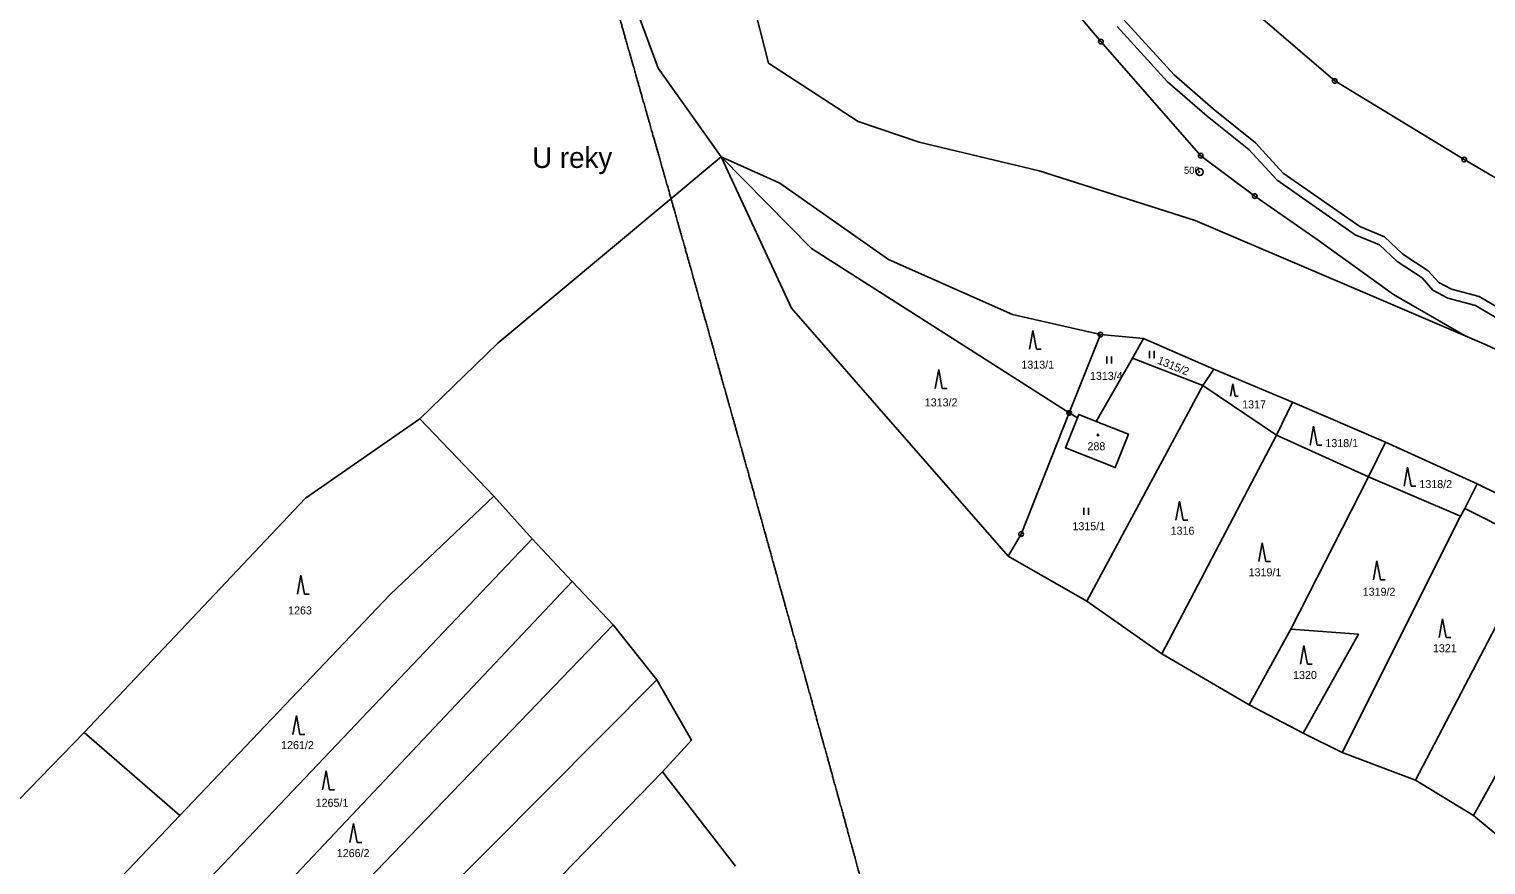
# Model space of a CAD drawing. Extents: x -680203 to -673936, y -1102717 to -1093650.
# Drawn here: x -676284 to -675974.5, y -1100041.7 to -1099864.2 of the extents above; entities that cross this region are included whole.
import ezdxf

# ---------------------------------------------------------------- set-up
doc = ezdxf.new("R2010")
doc.units = 0
for name, color, linetype in [('_Ideová část', 7, 'Continuous'), ('_Řešené území', 7, 'Continuous'), ('SOxx02xx_Koleje_param další_Popis10', 7, 'Continuous'), ('SOxx02xx_Staničení_Popis10', 7, 'Continuous'), ('SOxxxxxx_Koleje_hlavní_body_Popis10', 7, 'Continuous'), ('SOxxxxxx_Koleje_LN_parametry_Popis10', 7, 'Continuous'), ('SOxxxxxx_Koleje_param další_Popis10', 7, 'Continuous'), ('SOxxxxxx_Osa_bod_P', 7, 'Continuous'), ('x_prac', 7, 'Continuous')]:
    doc.layers.add(name, color=color, linetype=linetype)

msp = doc.modelspace()

# ---------------------------------------------------------------- linework, layer by layer
at = {"layer": '_Ideová část'}
msp.add_circle((-676417.7, -1099401.52), 1287.12, dxfattribs=at)
at = {"layer": '_Řešené území'}
for points in [[(-676159.4, -1099858.71), (-676158.26, -1099862.7), (-676157.11, -1099866.7), (-676155.97, -1099870.71)], [(-676155.97, -1099870.71), (-676154.83, -1099874.7), (-676153.69, -1099878.7), (-676152.55, -1099882.71)], [(-676152.55, -1099882.71), (-676151.41, -1099886.7), (-676150.28, -1099890.7), (-676149.14, -1099894.71)], [(-676149.14, -1099894.71), (-676148, -1099898.71), (-676146.87, -1099902.71), (-676145.73, -1099906.72)], [(-676145.73, -1099906.72), (-676144.6, -1099910.72), (-676143.47, -1099914.72), (-676142.34, -1099918.73)], [(-676142.34, -1099918.73), (-676141.21, -1099922.73), (-676140.08, -1099926.73), (-676138.95, -1099930.74)], [(-676138.95, -1099930.74), (-676137.82, -1099934.74), (-676136.7, -1099938.74), (-676135.57, -1099942.76)], [(-676135.57, -1099942.76), (-676134.45, -1099946.75), (-676133.32, -1099950.76), (-676132.2, -1099954.77)], [(-676132.2, -1099954.77), (-676131.08, -1099958.77), (-676129.96, -1099962.78), (-676128.83, -1099966.79)], [(-676128.83, -1099966.79), (-676127.72, -1099970.79), (-676126.6, -1099974.8), (-676125.48, -1099978.81)], [(-676125.48, -1099978.81), (-676124.37, -1099982.81), (-676123.25, -1099986.82), (-676122.13, -1099990.84)], [(-676122.13, -1099990.84), (-676121.02, -1099994.84), (-676119.91, -1099998.84), (-676118.8, -1100002.86)], [(-676118.8, -1100002.86), (-676117.69, -1100006.86), (-676116.58, -1100010.87), (-676115.47, -1100014.89)], [(-676115.47, -1100014.89), (-676114.36, -1100018.89), (-676113.25, -1100022.9), (-676112.14, -1100026.92)], [(-676112.14, -1100026.92), (-676111.04, -1100030.92), (-676109.94, -1100034.93), (-676108.83, -1100038.95)], [(-676108.83, -1100038.95), (-676107.73, -1100042.96), (-676106.63, -1100046.97), (-676105.53, -1100050.99)]]:
    msp.add_open_spline(points, degree=2, dxfattribs=at)
at = {"layer": 'SOxx02xx_Koleje_param další_Popis10'}
for centre, radius in [((-676056.24, -1099866.81), 0.5), ((-676056.24, -1099866.81), 0.0303), ((-676006.58, -1099875.18), 0.5), ((-676006.58, -1099875.18), 0.0303), ((-676035.03, -1099891.05), 0.5), ((-676035.03, -1099891.05), 0.0303), ((-675979.05, -1099891.89), 0.5), ((-675979.05, -1099891.89), 0.0303), ((-676035.26, -1099894.52), 0.75), ((-676035.26, -1099894.52), 0.03), ((-676023.56, -1099899.64), 0.5), ((-676023.56, -1099899.64), 0.0303), ((-676056.36, -1099929.04), 0.5), ((-676056.36, -1099929.04), 0.0303), ((-676062.99, -1099945.69), 0.5), ((-676062.99, -1099945.69), 0.0303), ((-676073.22, -1099971.41), 0.5), ((-676073.22, -1099971.41), 0.0303)]:
    msp.add_circle(centre, radius, dxfattribs=at)
at = {"layer": 'SOxxxxxx_Koleje_hlavní_body_Popis10'}
for p, q in [((-676070.69, -1099928.17), (-676071.44, -1099932.17)), ((-676069.94, -1099932.17), (-676070.69, -1099928.17)), ((-676069.94, -1099932.17), (-676068.94, -1099932.17)), ((-676045.94, -1099934.03), (-676045.94, -1099932.53)), ((-676044.94, -1099934.03), (-676044.94, -1099932.53)), ((-676090.7, -1099936.47), (-676091.45, -1099940.47)), ((-676089.95, -1099940.47), (-676090.7, -1099936.47)), ((-676055, -1099935.18), (-676055, -1099933.68)), ((-676054, -1099935.18), (-676054, -1099933.68)), ((-676028.24, -1099939.48), (-676028.74, -1099942.16)), ((-676027.74, -1099942.16), (-676028.24, -1099939.48)), ((-676089.95, -1099940.47), (-676088.95, -1099940.47)), ((-676027.74, -1099942.16), (-676027.07, -1099942.16)), ((-676011.06, -1099948.52), (-676011.81, -1099952.52)), ((-676010.31, -1099952.52), (-676011.06, -1099948.52)), ((-676010.31, -1099952.52), (-676009.31, -1099952.52)), ((-675991.09, -1099957.22), (-675991.84, -1099961.22)), ((-675990.34, -1099961.22), (-675991.09, -1099957.22)), ((-675990.34, -1099961.22), (-675989.34, -1099961.22)), ((-676059.86, -1099967.33), (-676059.86, -1099965.83)), ((-676058.86, -1099967.33), (-676058.86, -1099965.83)), ((-676039.55, -1099964.44), (-676040.3, -1099968.44)), ((-676038.8, -1099968.44), (-676039.55, -1099964.44)), ((-676038.8, -1099968.44), (-676037.8, -1099968.44)), ((-676021.98, -1099973.27), (-676022.73, -1099977.27)), ((-676021.23, -1099977.27), (-676021.98, -1099973.27)), ((-676021.23, -1099977.27), (-676020.23, -1099977.27)), ((-675997.62, -1099977.14), (-675998.37, -1099981.14)), ((-675996.87, -1099981.14), (-675997.62, -1099977.14)), ((-676226.2, -1099980.18), (-676226.95, -1099984.18)), ((-676225.45, -1099984.18), (-676226.2, -1099980.18)), ((-675996.87, -1099981.14), (-675995.87, -1099981.14)), ((-676225.45, -1099984.18), (-676224.45, -1099984.18)), ((-675983.67, -1099989.39), (-675984.42, -1099993.39)), ((-675982.92, -1099993.39), (-675983.67, -1099989.39)), ((-676013.13, -1099995.08), (-676013.88, -1099999.08)), ((-676012.38, -1099999.08), (-676013.13, -1099995.08)), ((-675982.92, -1099993.39), (-675981.92, -1099993.39)), ((-676012.38, -1099999.08), (-676011.38, -1099999.08)), ((-676227.17, -1100009.97), (-676227.92, -1100013.97)), ((-676226.42, -1100013.97), (-676227.17, -1100009.97)), ((-676226.42, -1100013.97), (-676225.42, -1100013.97)), ((-676220.86, -1100021.71), (-676221.61, -1100025.71)), ((-676220.11, -1100025.71), (-676220.86, -1100021.71)), ((-676220.11, -1100025.71), (-676219.11, -1100025.71)), ((-676215.04, -1100032.92), (-676215.79, -1100036.92)), ((-676214.29, -1100036.92), (-676215.04, -1100032.92)), ((-676214.29, -1100036.92), (-676213.29, -1100036.92))]:
    msp.add_line(p, q, dxfattribs=at)
at = {"layer": 'SOxxxxxx_Koleje_LN_parametry_Popis10'}
for points in [[(-676052.82, -1099863.62), (-676042.11, -1099875.34), (-676033.67, -1099882.65), (-676024.81, -1099889.77), (-676018.84, -1099896.28), (-676002.2, -1099907.86)], [(-675962.8, -1099928.71), (-675975.91, -1099920.99), (-675981.78, -1099919.43), (-675984.47, -1099918.02), (-675986.69, -1099915.48), (-675992.08, -1099911.97), (-675995.99, -1099908.29), (-676001.24, -1099906.1), (-676017.52, -1099894.76), (-676023.43, -1099888.31), (-676032.39, -1099881.11), (-676040.71, -1099873.9), (-676051.34, -1099862.26)], [(-676002.2, -1099907.86), (-675997.09, -1099909.99), (-675993.32, -1099913.55), (-675988.01, -1099917), (-675985.73, -1099919.62), (-675982.52, -1099921.31), (-675976.69, -1099922.85), (-675963.72, -1099930.49), (-675950.35, -1099936.38), (-675937.13, -1099943.88), (-675925.22, -1099950.4), (-675911.16, -1099956.48), (-675901.89, -1099961.49), (-675889.61, -1099968.11), (-675870.5, -1099977.94), (-675863.66, -1099981.35), (-675857.1, -1099984.63), (-675843.21, -1099991.31), (-675827.95, -1099999.23), (-675822.45, -1100002.36), (-675819.13, -1100004.45), (-675815.83, -1100006.42), (-675808.49, -1100010.96), (-675793.05, -1100019.98)]]:
    msp.add_lwpolyline(points, dxfattribs=at)
at = {"layer": 'SOxxxxxx_Koleje_param další_Popis10'}
msp.add_circle((-676056.87, -1099950.37), 0.175, dxfattribs=at)
at = {"layer": 'x_prac'}
for p, q in [((-676062.99, -1099945.69), (-676056.36, -1099929.04)), ((-676056.36, -1099929.04), (-676047.18, -1099929.88)), ((-676047.18, -1099929.88), (-676049.56, -1099934.04)), ((-676032.24, -1099936.43), (-676047.18, -1099929.88)), ((-676049.56, -1099934.04), (-676057.25, -1099947.48)), ((-676034.63, -1099939.88), (-676049.56, -1099934.04)), ((-676034.63, -1099939.88), (-676032.24, -1099936.43)), ((-676015.58, -1099943.43), (-676032.24, -1099936.43)), ((-676059.24, -1099985.69), (-676034.63, -1099939.88)), ((-676018.95, -1099950.44), (-676034.63, -1099939.88)), ((-676073.22, -1099971.41), (-676062.99, -1099945.69)), ((-676061.26, -1099946.76), (-676062.99, -1099945.69)), ((-676018.95, -1099950.44), (-676015.58, -1099943.43)), ((-675995.77, -1099951.87), (-676015.58, -1099943.43)), ((-676185.2, -1099963.39), (-676200.98, -1099946.98)), ((-676043.28, -1099996.89), (-676018.95, -1099950.44)), ((-676018.95, -1099950.44), (-675999.41, -1099959.24)), ((-675999.41, -1099959.24), (-675995.77, -1099951.87)), ((-675976.32, -1099960.75), (-675995.77, -1099951.87)), ((-676015.93, -1099991.65), (-675999.41, -1099959.24)), ((-675999.41, -1099959.24), (-675979.87, -1099967.59)), ((-675978.9, -1099965.99), (-675976.32, -1099960.75)), ((-675960.87, -1099968.39), (-675976.32, -1099960.75)), ((-676177.08, -1099972.46), (-676185.2, -1099963.39)), ((-675979.87, -1099967.59), (-675978.9, -1099965.99)), ((-675963.36, -1099973.81), (-675978.9, -1099965.99)), ((-676005, -1100017.85), (-675979.87, -1099967.59)), ((-676263.53, -1100063.36), (-676177.08, -1099972.46)), ((-676168.62, -1099981.53), (-676177.08, -1099972.46)), ((-676075.98, -1099976.08), (-676073.22, -1099971.41)), ((-676059.24, -1099985.69), (-676075.98, -1099976.08)), ((-675989.38, -1100023.71), (-675963.36, -1099973.81)), ((-676257.03, -1100075.25), (-676168.62, -1099981.53)), ((-676159.86, -1099990.68), (-676168.62, -1099981.53)), ((-675977.12, -1100031.17), (-675948.97, -1099980.64)), ((-676043.28, -1099996.89), (-676059.24, -1099985.69)), ((-676254.56, -1100089.03), (-676159.86, -1099990.68)), ((-676150.59, -1100002.38), (-676159.86, -1099990.68)), ((-676024.72, -1100007.72), (-676015.93, -1099991.65)), ((-676024.72, -1100007.72), (-676043.28, -1099996.89)), ((-676013.26, -1100013.68), (-676024.72, -1100007.72)), ((-676327.02, -1100069.84), (-676272.3, -1100013.6)), ((-676251.94, -1100031.21), (-676272.3, -1100013.6)), ((-676005, -1100017.85), (-676013.26, -1100013.68)), ((-675989.38, -1100023.71), (-676005, -1100017.85)), ((-676181.13, -1100054.53), (-676149.37, -1100021.9)), ((-676133.9, -1100041.95), (-676149.37, -1100021.9)), ((-675977.12, -1100031.17), (-675989.38, -1100023.71)), ((-676251.94, -1100031.21), (-676283.72, -1100064.46)), ((-675964.81, -1100041.41), (-675977.12, -1100031.17))]:
    msp.add_line(p, q, dxfattribs=at)
for points in [[(-676136.92, -1099891.31), (-676150.34, -1099872.48), (-676174.34, -1099807.56), (-676189.96, -1099776.98), (-676210.15, -1099738.03), (-676236.4, -1099687.15), (-676258.35, -1099661.79), (-676281.13, -1099634.4), (-676310.99, -1099577.62), (-676343.06, -1099502.08), (-676371.06, -1099463.4), (-676414.83, -1099431.65), (-676528.16, -1099352.79), (-676653.08, -1099275.13), (-676685.89, -1099268.24), (-676728.97, -1099246.24)], [(-676199.67, -1099537.72), (-676191.18, -1099544.23), (-676184.32, -1099561.54), (-676154.89, -1099602.92), (-676148.21, -1099623.96), (-676138.79, -1099649.53), (-676132.07, -1099670.16), (-676120.64, -1099701.37), (-676108.14, -1099736.46), (-676092.98, -1099779.72), (-676083.74, -1099799.5), (-676060.28, -1099820.73), (-676037.23, -1099848.82), (-676006.58, -1099875.18), (-675979.05, -1099891.89), (-675951.53, -1099908.03), (-675897.37, -1099934.31), (-675867.27, -1099948.26), (-675853, -1099954.61), (-675776.91, -1099991.79)], [(-676117.71, -1099763.31), (-676102.33, -1099798.68), (-676094.68, -1099812.86), (-676085.91, -1099827.61), (-676074.87, -1099843.37), (-676065.95, -1099855.23), (-676056.24, -1099866.81), (-676035.03, -1099891.05), (-676023.56, -1099899.64), (-676010.31, -1099908.88), (-675994.07, -1099920.54), (-675978.88, -1099929.3)], [(-675978.88, -1099929.3), (-675999.65, -1099920.41), (-676036.21, -1099904.82), (-676069.38, -1099894.28), (-676094.9, -1099888.18), (-676107.83, -1099883.82), (-676126.91, -1099871.38), (-676129.61, -1099860.54), (-676133.99, -1099833.8), (-676139.1, -1099820.18), (-676144.04, -1099808.21), (-676153.36, -1099787.75)], [(-675978.88, -1099929.3), (-675999.65, -1099920.41), (-676036.21, -1099904.82), (-676069.38, -1099894.28), (-676094.9, -1099888.18), (-676107.83, -1099883.82), (-676126.91, -1099871.38), (-676129.61, -1099860.54), (-676133.99, -1099833.8), (-676139.1, -1099820.18), (-676144.04, -1099808.21), (-676153.36, -1099787.75)], [(-676200.98, -1099946.98), (-676184.37, -1099930.9), (-676136.92, -1099891.31)], [(-676075.98, -1099976.08), (-676121.96, -1099923.46), (-676136.92, -1099891.31)], [(-676136.92, -1099891.31), (-676117.72, -1099910.75), (-676079.88, -1099934.93), (-676062.99, -1099945.69)], [(-676056.36, -1099929.04), (-676075.04, -1099924.81), (-676101.4, -1099913.11), (-676124.45, -1099896.91), (-676136.92, -1099891.31)], [(-675978.88, -1099929.3), (-675974.37, -1099931.23), (-675931.49, -1099951.16), (-675906.96, -1099963.1), (-675861.46, -1099988.51), (-675843.68, -1099998.35), (-675832.62, -1100005.56), (-675812.15, -1100019.19), (-675802.21, -1100030.11), (-675777.48, -1100056.88), (-675763.27, -1100074.81), (-675746.73, -1100095.56), (-675716.37, -1100123.87), (-675677.09, -1100159.95), (-675660.84, -1100178.25), (-675650.93, -1100184.82), (-675626.35, -1100211.55)], [(-675978.88, -1099929.3), (-675974.37, -1099931.23), (-675931.49, -1099951.16), (-675906.96, -1099963.1), (-675861.46, -1099988.51), (-675843.68, -1099998.35), (-675832.62, -1100005.56), (-675812.15, -1100019.19), (-675802.21, -1100030.11), (-675777.48, -1100056.88), (-675763.27, -1100074.81), (-675746.73, -1100095.56), (-675716.37, -1100123.87), (-675677.09, -1100159.95), (-675660.84, -1100178.25), (-675650.93, -1100184.82), (-675626.35, -1100211.55)], [(-676272.3, -1100013.6), (-676225.26, -1099963.8), (-676200.98, -1099946.98)], [(-676061.26, -1099946.76), (-676063.78, -1099953.1), (-676053.2, -1099957.31), (-676050.38, -1099950.22), (-676057.25, -1099947.48)], [(-676057.25, -1099947.48), (-676060.96, -1099946), (-676061.26, -1099946.76)], [(-676185.2, -1099963.39), (-676207.29, -1099984.27), (-676251.94, -1100031.21)], [(-676015.93, -1099991.65), (-676001.55, -1099992.71), (-676013.26, -1100013.68)], [(-676264.58, -1100120.51), (-676209.8, -1100061.91), (-676150.59, -1100002.38)], [(-676149.37, -1100021.9), (-676143.2, -1100015.19), (-676150.59, -1100002.38)]]:
    msp.add_lwpolyline(points, dxfattribs=at)

# ---------------------------------------------------------------- texts
at = {"layer": 'SOxx02xx_Koleje_param další_Popis10'}
msp.add_text('506', height=1.5, dxfattribs=at).set_placement((-676038.6, -1099894.9))
at = {"layer": 'SOxx02xx_Staničení_Popis10'}
msp.add_text('U reky', height=4.4, dxfattribs=at).set_placement((-676177.08, -1099893.66))
at = {"layer": 'SOxxxxxx_Osa_bod_P'}
for s, p in [('1313/1', (-676073.15, -1099936.29)), ('1313/4', (-676058.58, -1099938.67)), ('1313/2', (-676093.68, -1099944.3)), ('1317', (-676026.24, -1099944.73)), ('288', (-676059.11, -1099953.62)), ('1318/1', (-676008.56, -1099952.95)), ('1318/2', (-675988.59, -1099961.65)), ('1315/1', (-676062.3, -1099970.6)), ('1316', (-676041.44, -1099971.56)), ('1319/1', (-676024.87, -1099980.4)), ('1319/2', (-676000.63, -1099984.52)), ('1263', (-676228.94, -1099988.49)), ('1321', (-675985.72, -1099996.52)), ('1320', (-676015.42, -1100002.21)), ('1261/2', (-676230.42, -1100017.09)), ('1265/1', (-676223.09, -1100029.35)), ('1266/2', (-676218.6, -1100040.04))]:
    msp.add_text(s, height=1.7, dxfattribs=at).set_placement(p)
msp.add_text('1315/2', height=1.7, rotation=338, dxfattribs=at).set_placement((-676044.39, -1099935.18))

doc.saveas('drawing.dxf')
